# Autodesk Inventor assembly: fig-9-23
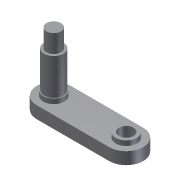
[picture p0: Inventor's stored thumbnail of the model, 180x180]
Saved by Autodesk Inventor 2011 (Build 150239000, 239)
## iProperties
Shininess: 64.0
Length Units: 11269
Angle Units: 11279
Time Units: 11290
Mass Units: 11283
Length Display Precision: 3
Angle Display Precision: 2
Created: 2002-01
Part Number: fig-9-23
Document SubType Name: Assembly
Designer: ***
Density: 0.0
Volumn: 0.0
Area: 0.0
PropertySet Name: Model Information
Control State: 0
Master: False
Checked Out: False
Author: ***
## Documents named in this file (3)
- C:\Users\CADSoft\Desktop\part files\c09-inv-2011-prt\fig-9-23.iam
- C:\Users\CADSoft\Desktop\inventor\c09-inv-2010-prt\c09\Part5.ipt
- C:\Users\CADSoft\Desktop\inventor\c09-inv-2010-prt\c09\Part6.ipt
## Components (2 placed, 2 different names)
1. Part5:1 — Insert:1
2. Part6:1 — Insert:1
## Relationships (1: Insert 1)
- Insert:1: Part5:1 ↔ Part6:1
